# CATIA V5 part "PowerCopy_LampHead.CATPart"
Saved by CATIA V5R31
Part number: LampHead
Bounding box of the stored display mesh (mm): x -39.996 to 39.996, y -64.64 to 12.108, z 0 to 91.961
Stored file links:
  C:\Users\patol451\OneDrive - Linköpings universitet\Nuvarande kurser\Exjobb\LampCATIA\PowerCopy_LampHead.CATPart
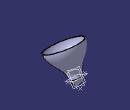
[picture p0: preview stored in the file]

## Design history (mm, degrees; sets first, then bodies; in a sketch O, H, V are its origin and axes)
Parameters
  diameter = 10 mm
  headAdjust = 30 deg
  headDiameter = 80 mm
  headLength = 60 mm
  offset = 2 mm
Set1 "Reference Support"
  AxisSystem1: origin (0, 0, 20), X (1, 0, 0), Y (0, 1, 0), Z (0, 0, 1)
  Point1 "PointLeft": (-20, 0, 20)
  Rotate1 "HeadAxisSystem": Axis edge [XY plane of AxisSystem1 | ZX plane of AxisSystem1], ToTransfor AxisSystem1, Angle 30 {= headAdjust}
  Translate1: ToTransfor Rotate1, FirstPoint Point5
  Point2 "P1": (0, 0, 0)
Set2 "References"
  Plane1 "xy": type Offset, RefPlane face of Translate1, Offset 0
  Plane2 "yz": type Offset, RefPlane face of Translate1, Offset 0
  Plane3 "zx": type Offset, RefPlane face of Translate1, Offset 0
  Point3 "P1": type OnPlane, Support Plane3, RefPoint Point5, H 0, V -20, Direction (-1, 0, 0)
  Point4 "PointRight": (20, 0, 20)
  Point5 "PointMiddle": (0, 0, 20)
Set3 "Placement"
  Point6 "PlacementPoint": (0, 0, 0), relative to Point4
Set4 "Geo_1"
  AxisSystem2: origin (0, 0, 20), X (1, 0, 0), Y (0, 0.866, 0.5), Z (0, -0.5, 0.866)
  Point7: (-7.5 {= -3*diameter /4}, 0, 0), relative to Point4, in AxisSystem2
  Point8: (0, 0, 7.5 {= 3*diameter /4}), relative to Point3, in AxisSystem2
  Point9: (40 {= headDiameter /2}, 0, 60 {= headLength}), relative to Point5, in AxisSystem2
  Curve1: Elements (Point7; Point9)
  Curve2: Elements (Point8; Point7)
  Join1: Elements (Curve1; Curve2)
  3DCurveOffset1: Curve Join1, Direction Plane3, Offset 2, CornerRadius 1, CornerTension 0.5
  Split1: ToCut 3DCurveOffset1, Cutting Plane1
  Point10: (-6 {= -offset *3}, 0, 0), relative to Point7, in AxisSystem2
  Point11: (8 {= offset *4}, 0, 38.1818 {= 7*headLength /11}), relative to Point10, in AxisSystem2
  Point12: (0, 0, 43.6364 {= headLength *8/11}), relative to Point5, in AxisSystem2
  Curve3: Elements (Point10; Point11)
  Curve4: Elements (Point11; Point12)
  Line1: type PtPt, FirstPoint Point12, SecondPoint Point8
  Line2: type PtPt, FirstPoint Point10, SecondPoint Point7
  Split2: ToCut Line2, Cutting Split1
  Line3: type PtPt, FirstPoint vertex of 3DCurveOffset1, SecondPoint Point9
  Join2: Elements (Join1; Line3; Split1; Curve3; Curve4; Line1; Split2)
Body1 (main body)
  Shaft1: profile Join2, axis Line1, angle 360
